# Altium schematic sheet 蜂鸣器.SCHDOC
size A4
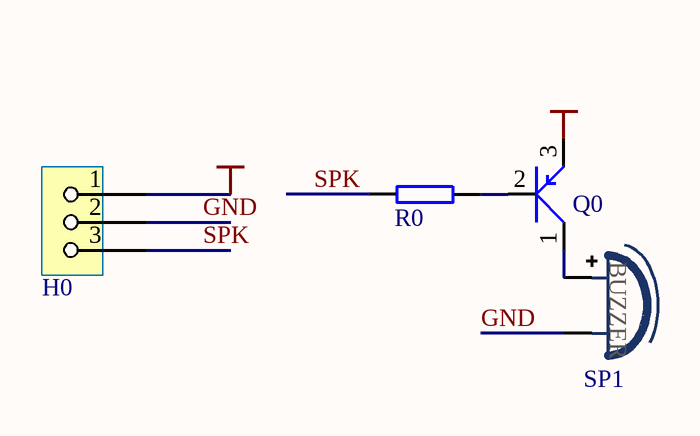
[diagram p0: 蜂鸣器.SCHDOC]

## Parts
H0  DIS3  [DIS3]  (value not drawn)
Q0  PNP  [PNP]  (value not drawn)
R0  RESIS  [resistor-0.4]  (value not drawn)
SP1  BUZZEN  [buzzen]  (value not drawn)

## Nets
VCC: H0.1 Q0.3
GND: H0.2 SP1.2
SPK: H0.3 R0.1
NetQ0_1: Q0.1 SP1.1
NetQ0_2: Q0.2 R0.2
